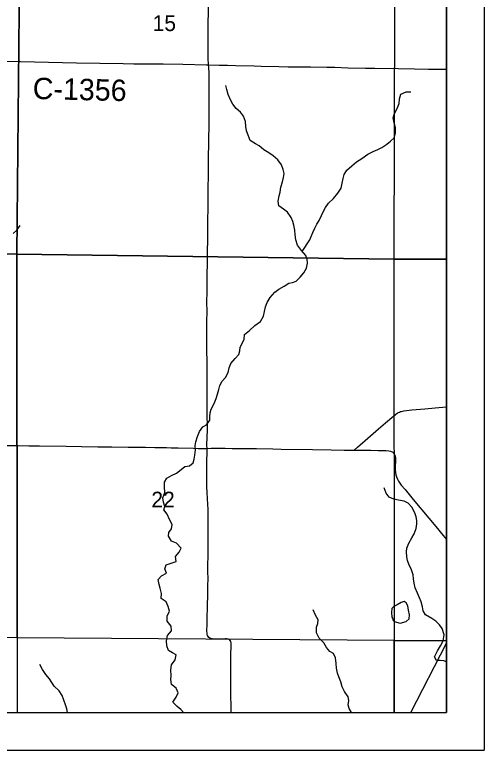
# Model space of a CAD drawing. Extents: x 0 to 70.2, y 0 to 31.4.
# Drawn here: x 7.753 to 9, y 14 to 15.952 of the extents above; entities that cross this region are included whole.
import ezdxf

# ---------------------------------------------------------------- set-up
doc = ezdxf.new("R2010")
doc.units = 0
for name, color, linetype in [('GM_X_County_Road', 7, 'Continuous'), ('GM_X_County_Road_Text', 7, 'Continuous'), ('GM_X_Minor_Lake', 7, 'Continuous'), ('GM_X_Minor_River', 7, 'Continuous'), ('GM_X_Rail_Line', 7, 'Continuous'), ('GM_X_Section', 7, 'Continuous'), ('GM_X_Section_Text', 7, 'Continuous'), ('GM_X_State_Route', 7, 'Continuous'), ('GM_X_Township_Road', 7, 'Continuous'), ('SH_Cut_Line', 7, 'Continuous'), ('SH_Data', 7, 'Continuous')]:
    doc.layers.add(name, color=color, linetype=linetype)

msp = doc.modelspace()

# ---------------------------------------------------------------- linework, layer by layer
at = {"layer": 'GM_X_County_Road'}
for points in [[(7.6473, 15.8303), (7.6903, 15.8292), (7.7214, 15.8286), (7.7679, 15.8277), (7.8052, 15.8268), (7.917, 15.8247), (7.9789, 15.8235), (8.041, 15.8223), (8.0691, 15.822), (8.1468, 15.8216), (8.1996, 15.8212), (8.2617, 15.8195), (8.2673, 15.8194)], [(8.2673, 15.8194), (8.2958, 15.8185), (8.3175, 15.8179), (8.3393, 15.8175), (8.389, 15.8165), (8.4076, 15.8159), (8.4542, 15.8146), (8.479, 15.8141), (8.5132, 15.8136), (8.538, 15.8136), (8.5815, 15.8128), (8.6032, 15.8126), (8.6374, 15.8116), (8.684, 15.8107), (8.7088, 15.81), (8.7709, 15.8095), (8.8144, 15.8086), (8.8517, 15.8079), (8.8982, 15.8074), (8.9, 15.8074)], [(7.7156, 14.809), (7.7622, 14.8086), (7.7901, 14.8084), (7.8181, 14.8082), (7.8895, 14.8067), (7.9298, 14.806), (7.9733, 14.8052), (8.0106, 14.805), (8.0541, 14.8048), (8.0727, 14.8046), (8.1005, 14.8043), (8.1253, 14.8039), (8.1562, 14.8033), (8.1686, 14.8031), (8.1872, 14.8029), (8.2275, 14.8016), (8.2399, 14.8013), (8.2586, 14.8012), (8.2636, 14.8013)], [(8.2636, 14.8013), (8.2741, 14.8014), (8.2896, 14.8014), (8.3113, 14.8014), (8.33, 14.8012), (8.3578, 14.8009), (8.395, 14.8005), (8.4384, 14.7998), (8.4602, 14.7995), (8.5439, 14.7981), (8.5936, 14.7972), (8.6277, 14.7967), (8.6542, 14.7968)], [(8.6542, 14.7968), (8.6711, 14.7964), (8.6985, 14.7963), (8.7178, 14.7958), (8.7394, 14.7954), (8.7464, 14.795), (8.7509, 14.7936), (8.7568, 14.7909), (8.7607, 14.7865), (8.7632, 14.7811), (8.764, 14.7764), (8.7642, 14.7717), (8.7641, 14.7674), (8.7635, 14.7532), (8.7633, 14.7437), (8.7639, 14.7368), (8.7649, 14.7312), (8.7667, 14.7257), (8.7694, 14.7198), (8.7724, 14.7143), (8.7758, 14.709), (8.7796, 14.704), (8.7895, 14.6921), (8.8114, 14.6659), (8.853, 14.6157), (8.8709, 14.5942), (8.8907, 14.5704), (8.9, 14.5595)]]:
    msp.add_lwpolyline(points, dxfattribs=at)
at = {"layer": 'GM_X_Minor_Lake'}
for points in [[(8.7608, 14.3416), (8.7764, 14.3374), (8.7922, 14.3416), (8.8, 14.349), (8.8013, 14.3597), (8.7987, 14.3717), (8.7969, 14.3838), (8.7926, 14.3913), (8.7868, 14.3946), (8.779, 14.3918), (8.7689, 14.3858), (8.7595, 14.3814), (8.7543, 14.376), (8.7538, 14.3654)], [(8.7538, 14.3654), (8.7546, 14.3533), (8.7558, 14.3502), (8.7581, 14.3446), (8.7608, 14.3416)]]:
    msp.add_lwpolyline(points, dxfattribs=at)
at = {"layer": 'GM_X_Minor_River'}
for points in [[(8.2049, 14.7531), (8.2169, 14.7549), (8.2266, 14.7631), (8.229, 14.7726), (8.2315, 14.7829), (8.2326, 14.7977), (8.232, 14.808), (8.234, 14.819), (8.2386, 14.8328), (8.2433, 14.8458), (8.2524, 14.8582), (8.2625, 14.8633), (8.2714, 14.8757), (8.2707, 14.8855), (8.2717, 14.8954), (8.2741, 14.9057), (8.2821, 14.9203), (8.2874, 14.9334), (8.2917, 14.9452), (8.2949, 14.9571), (8.2976, 14.9678), (8.3038, 14.9797), (8.3123, 14.9897), (8.3199, 15.0028), (8.3227, 15.0154), (8.327, 15.0261), (8.3384, 15.0401), (8.3476, 15.0502), (8.3504, 15.0601), (8.3517, 15.0696), (8.3568, 15.0796), (8.3618, 15.0907), (8.3627, 15.1033), (8.3765, 15.1142), (8.3902, 15.1274), (8.4058, 15.1384), (8.4139, 15.1519), (8.4162, 15.1641), (8.4186, 15.1771), (8.4229, 15.1882), (8.4313, 15.2017), (8.4434, 15.216), (8.4539, 15.2234), (8.4681, 15.2314), (8.4808, 15.2393), (8.4906, 15.2414), (8.5004, 15.245), (8.5111, 15.2555), (8.5203, 15.2671), (8.5276, 15.2798), (8.5303, 15.2932), (8.5297, 15.303), (8.5257, 15.3128), (8.5148, 15.3262), (8.5038, 15.3404), (8.4993, 15.3551), (8.4975, 15.3679), (8.4968, 15.3801), (8.4939, 15.394), (8.491, 15.4038), (8.4873, 15.414), (8.4775, 15.4278), (8.4664, 15.4359), (8.4544, 15.4447), (8.4522, 15.4575), (8.4553, 15.4713), (8.4574, 15.4816), (8.4597, 15.4945), (8.4643, 15.5087), (8.4667, 15.5205), (8.468, 15.5308), (8.4654, 15.5413), (8.4614, 15.5534), (8.452, 15.5668), (8.4392, 15.5775), (8.4273, 15.5856), (8.4146, 15.5936), (8.4022, 15.6044), (8.3926, 15.6094), (8.378, 15.6186), (8.3728, 15.6321), (8.3687, 15.6442), (8.3669, 15.6559), (8.3659, 15.6688), (8.3602, 15.6831), (8.352, 15.6931), (8.3408, 15.7035), (8.3318, 15.715), (8.3259, 15.7259), (8.3199, 15.7402), (8.3158, 15.7537), (8.3132, 15.7643)], [(8.5165, 15.3241), (8.5368, 15.3544), (8.54, 15.364), (8.5447, 15.374), (8.5498, 15.3855), (8.5548, 15.3959), (8.5618, 15.4059), (8.5672, 15.4197), (8.573, 15.4312), (8.5784, 15.4408), (8.5861, 15.452), (8.5998, 15.4641), (8.6113, 15.4788), (8.6197, 15.4919), (8.6228, 15.5052), (8.6247, 15.5178), (8.6279, 15.5285), (8.6349, 15.5397), (8.6482, 15.551), (8.6609, 15.5615), (8.6743, 15.571), (8.6907, 15.5824), (8.7049, 15.5888), (8.7173, 15.5948), (8.7274, 15.5999), (8.7409, 15.6082), (8.7505, 15.6164), (8.7602, 15.6258), (8.7644, 15.6391), (8.7641, 15.652), (8.7604, 15.6656), (8.7582, 15.6788), (8.7617, 15.6899), (8.7682, 15.7034), (8.7736, 15.7164), (8.7748, 15.7293), (8.7787, 15.7416), (8.7922, 15.7476), (8.8051, 15.7471)], [(7.7487, 15.3718), (7.7587, 15.38), (7.7675, 15.3927)], [(8.2006, 14.1), (8.1937, 14.1084), (8.184, 14.1166), (8.1731, 14.1281), (8.1812, 14.1408), (8.1866, 14.1527), (8.1814, 14.1651), (8.1687, 14.1743), (8.1676, 14.1875), (8.1685, 14.1974), (8.167, 14.2133), (8.1693, 14.227), (8.1789, 14.2401), (8.1816, 14.2535), (8.172, 14.259), (8.1613, 14.2644), (8.1564, 14.2776), (8.1561, 14.2905), (8.1584, 14.3045), (8.1695, 14.317), (8.1681, 14.3298), (8.1572, 14.3428), (8.1576, 14.3558), (8.1641, 14.3692), (8.1604, 14.3812), (8.1548, 14.3944), (8.1421, 14.4032), (8.1426, 14.4165), (8.1392, 14.4301), (8.136, 14.4399), (8.1334, 14.4535), (8.143, 14.4632), (8.1561, 14.4703), (8.1513, 14.4812), (8.1552, 14.4919), (8.1812, 14.5013), (8.1797, 14.5141), (8.1897, 14.5254), (8.1951, 14.5361), (8.1827, 14.5495), (8.1689, 14.5552), (8.1614, 14.5684), (8.1623, 14.5782), (8.1693, 14.5879), (8.1713, 14.5993), (8.1638, 14.6128), (8.1574, 14.6263), (8.1492, 14.6379), (8.1512, 14.6474), (8.1483, 14.6587), (8.1462, 14.6701), (8.1515, 14.6842), (8.1504, 14.6994), (8.1509, 14.7112), (8.1563, 14.7219), (8.1687, 14.729), (8.1825, 14.7358), (8.1944, 14.7452), (8.2049, 14.7531)], [(8.9, 14.2346), (8.8924, 14.2377), (8.8829, 14.2386), (8.8727, 14.238), (8.8675, 14.2481), (8.8759, 14.2643), (8.8839, 14.277), (8.8904, 14.2908), (8.8931, 14.3068), (8.8878, 14.323), (8.8807, 14.3327), (8.8714, 14.3431), (8.8602, 14.3501), (8.8441, 14.3595), (8.8378, 14.3704), (8.836, 14.3806), (8.8327, 14.3942), (8.8283, 14.4047), (8.8223, 14.4171), (8.8163, 14.431), (8.8137, 14.4434), (8.812, 14.4548), (8.811, 14.4654), (8.8069, 14.4789), (8.7997, 14.494), (8.7961, 14.5037), (8.7939, 14.5136), (8.7933, 14.5264), (8.7945, 14.5363), (8.7999, 14.5494), (8.8079, 14.564), (8.8134, 14.5747), (8.8191, 14.5885), (8.8211, 14.6007), (8.8212, 14.6102), (8.8191, 14.62), (8.8151, 14.6306), (8.8072, 14.6448), (8.7982, 14.656), (8.7875, 14.661), (8.7723, 14.6637), (8.7601, 14.6661), (8.7471, 14.6722), (8.7396, 14.6826), (8.7336, 14.6962)], [(8.6475, 14.1), (8.6411, 14.1111), (8.6382, 14.1209), (8.6402, 14.1323), (8.6381, 14.1421), (8.6283, 14.1556), (8.6223, 14.1683), (8.619, 14.1815), (8.6134, 14.1951), (8.6101, 14.2048), (8.6076, 14.2177), (8.6065, 14.2306), (8.605, 14.245), (8.5991, 14.2566), (8.5895, 14.2624), (8.5809, 14.2732), (8.5742, 14.2856), (8.5617, 14.2978), (8.5542, 14.3121), (8.5539, 14.3265), (8.5574, 14.3364), (8.5583, 14.3463), (8.5512, 14.359), (8.5452, 14.3726)], [(7.893, 14.1), (7.8909, 14.1096), (7.888, 14.1202), (7.8835, 14.1333), (7.8787, 14.145), (7.8708, 14.1581), (7.8577, 14.1699), (7.851, 14.1796), (7.8455, 14.1893), (7.8357, 14.2013), (7.8263, 14.2147), (7.8196, 14.2274)]]:
    msp.add_lwpolyline(points, dxfattribs=at)
at = {"layer": 'GM_X_Rail_Line'}
msp.add_line((8.8045, 14.1), (8.9, 14.2841), dxfattribs=at)
at = {"layer": 'GM_X_Section'}
for points in [[(6.7778, 16.3386), (7.7683, 16.3298), (7.7584, 15.3168), (6.7706, 15.321)], [(7.7683, 16.3298), (8.7624, 16.321), (8.7601, 15.3035), (7.7584, 15.3168)], [(6.7706, 15.321), (7.7584, 15.3168), (7.7596, 14.2988), (6.7617, 14.3072)], [(8.7601, 15.3035), (8.7604, 14.2912), (7.7596, 14.2988), (7.7584, 15.3168)]]:
    msp.add_lwpolyline(points, close=True, dxfattribs=at)
at = {"layer": 'GM_X_Section_Text'}
msp.add_lwpolyline([(6.7623, 14.1), (8.9, 14.1), (8.9, 18.3173)], dxfattribs=at)
at = {"layer": 'GM_X_State_Route'}
for points in [[(8.9, 15.3035), (8.9, 16.3205), (8.7624, 16.321), (8.7601, 15.3035)], [(8.9, 14.2909), (8.9, 15.3035), (8.7601, 15.3035), (8.7604, 14.2912)], [(7.7593, 14.1), (8.761, 14.1), (8.7604, 14.2912), (7.7596, 14.2988)], [(8.761, 14.1), (8.9, 14.1), (8.9, 14.2909), (8.7604, 14.2912)]]:
    msp.add_lwpolyline(points, close=True, dxfattribs=at)
at = {"layer": 'GM_X_Township_Road'}
for points in [[(8.2673, 15.8194), (8.2671, 15.8216), (8.2666, 15.8341), (8.2666, 15.8652), (8.2669, 15.9149), (8.2672, 15.9739)], [(8.2636, 14.8013), (8.2632, 14.8099), (8.2635, 14.8315), (8.2644, 14.8491), (8.2645, 14.8665), (8.2641, 14.8842), (8.264, 14.9155), (8.2635, 14.9527), (8.2635, 14.9652), (8.2636, 14.9744), (8.2636, 14.9988), (8.2636, 15.0203), (8.2635, 15.0327), (8.2628, 15.0605), (8.2628, 15.0858), (8.2629, 15.1132), (8.2633, 15.1409), (8.2635, 15.1619), (8.2632, 15.1921), (8.2635, 15.2151), (8.2637, 15.234), (8.2638, 15.2527), (8.2639, 15.2681), (8.2644, 15.287), (8.2645, 15.2994), (8.2649, 15.3145), (8.2658, 15.3639), (8.2658, 15.3889), (8.266, 15.4168), (8.2661, 15.4292), (8.2669, 15.4882), (8.2671, 15.5286), (8.2674, 15.5565), (8.2677, 15.572), (8.2685, 15.6124), (8.2692, 15.6678), (8.2692, 15.6855), (8.2692, 15.6977), (8.2693, 15.7225), (8.2694, 15.738), (8.2695, 15.7628), (8.2691, 15.7969), (8.2681, 15.8124), (8.2673, 15.8194)], [(8.6542, 14.7968), (8.6632, 14.8046), (8.6906, 14.8285), (8.7189, 14.8528), (8.7379, 14.8688), (8.7545, 14.8829), (8.7639, 14.891), (8.7689, 14.8947), (8.7716, 14.8962), (8.7744, 14.8976), (8.7773, 14.8987), (8.7802, 14.8995), (8.7863, 14.9007), (8.8079, 14.9033), (8.8419, 14.9066), (8.8697, 14.9092), (8.9, 14.9118)], [(8.3279, 14.1), (8.3276, 14.1175), (8.3267, 14.1454), (8.3265, 14.1547), (8.3264, 14.1873), (8.3264, 14.2041), (8.3267, 14.2133), (8.3264, 14.2231), (8.3267, 14.2331), (8.3265, 14.2434), (8.3268, 14.2553), (8.3273, 14.2752), (8.3274, 14.2818), (8.3273, 14.2855), (8.3265, 14.2887), (8.3252, 14.2918), (8.3232, 14.2939), (8.3206, 14.2948), (8.3176, 14.2953), (8.3148, 14.2955), (8.3115, 14.2955), (8.3016, 14.2953), (8.2816, 14.2949), (8.2773, 14.2954), (8.2737, 14.2963), (8.2712, 14.2978), (8.2685, 14.2997), (8.2665, 14.3023), (8.2651, 14.305), (8.2641, 14.3082), (8.2636, 14.3113), (8.2634, 14.3149), (8.2641, 14.3362), (8.2643, 14.3486), (8.2651, 14.3826), (8.2656, 14.4136), (8.2658, 14.4385), (8.2661, 14.4541), (8.266, 14.4757), (8.266, 14.4912), (8.2662, 14.5159), (8.2662, 14.5316), (8.2663, 14.5438), (8.2666, 14.5626), (8.2665, 14.5812), (8.2666, 14.5909), (8.2666, 14.6149), (8.2661, 14.64), (8.2656, 14.6521), (8.2649, 14.6686), (8.2638, 14.6843), (8.2629, 14.6992), (8.2628, 14.7209), (8.263, 14.7477), (8.2634, 14.7701), (8.2636, 14.7886), (8.2636, 14.7977), (8.2636, 14.8013)]]:
    msp.add_lwpolyline(points, dxfattribs=at)
at = {"layer": 'SH_Cut_Line'}
msp.add_lwpolyline([(6.7623, 14.1), (8.9, 14.1), (8.9, 20.9)], dxfattribs=at)
at = {"layer": 'SH_Data'}
for p, q in [((9, 21), (9, 14)), ((8.9, 20.9), (8.9, 14.1)), ((2.1, 14.1), (8.9, 14.1)), ((2, 14), (9, 14))]:
    msp.add_line(p, q, dxfattribs=at)

# ---------------------------------------------------------------- texts
at = {"layer": 'GM_X_County_Road_Text'}
msp.add_text('C-1356', height=0.05682, rotation=358.6361, dxfattribs=at).set_placement((7.8001, 15.7286))
at = {"layer": 'GM_X_Section_Text'}
for s, p in [('15', (8.1189, 15.9088)), ('22', (8.1156, 14.6444))]:
    msp.add_text(s, height=0.04186, rotation=0, dxfattribs=at).set_placement(p)

doc.saveas('drawing.dxf')
